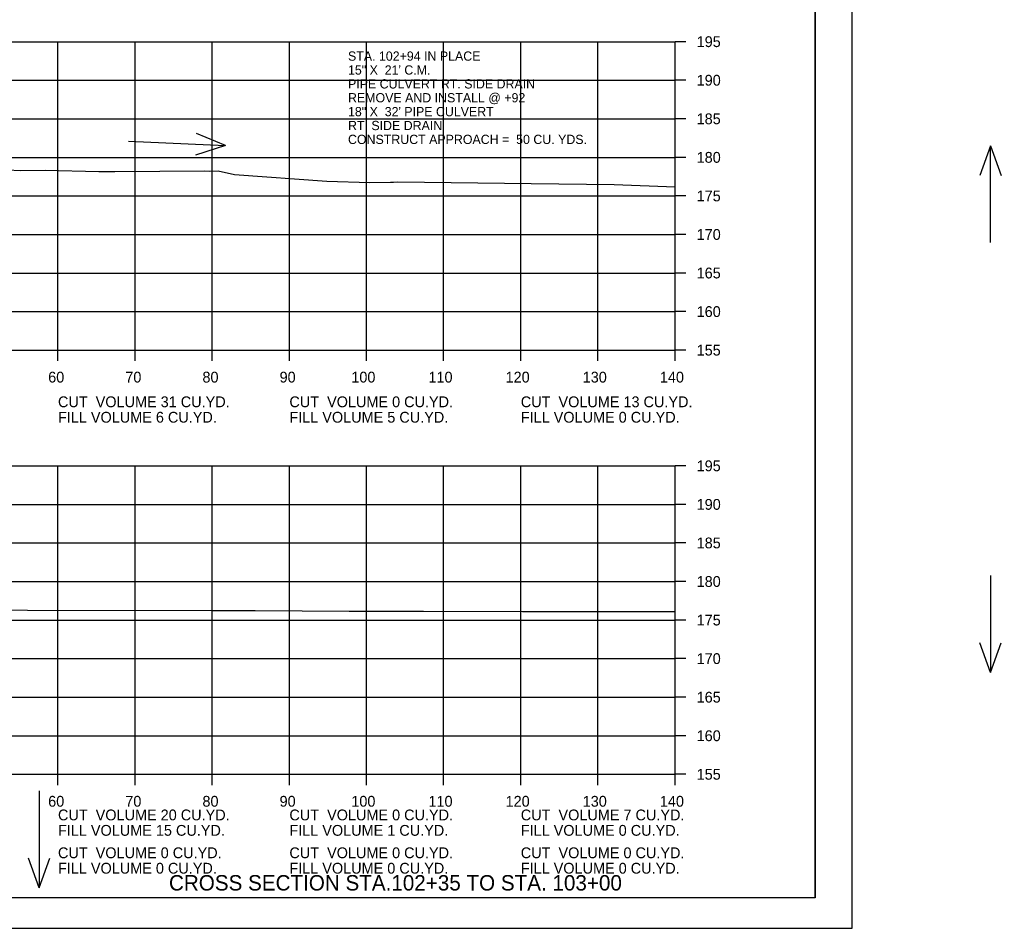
# Model space of a CAD drawing. Extents: x 915787 to 919910, y 133456 to 136717.
# Drawn here: x 916469 to 916596.3, y 133456 to 133573.9 of the extents above; entities that cross this region are included whole.
import ezdxf

# ---------------------------------------------------------------- set-up
doc = ezdxf.new("R2010")
doc.units = 0
for name, color, linetype in [('R_Axis', 7, 'Continuous'), ('R_Axis Annot', 7, 'Continuous'), ('R_Border', 7, 'Continuous'), ('R_Border Notes', 7, 'Continuous'), ('R_Draft', 7, 'Continuous'), ('R_Exist Surface', 7, 'Continuous'), ('R_Grid', 7, 'Continuous'), ('R_No Plot', 7, 'Continuous'), ('R_Water Annot', 7, 'Continuous')]:
    doc.layers.add(name, color=color, linetype=linetype)

msp = doc.modelspace()

# ---------------------------------------------------------------- linework, layer by layer
at = {"layer": 'R_Axis'}
for p, q in [((916553.98, 133531.01), (916553.98, 133571.01)), ((916555.38, 133571.01), (916553.98, 133571.01)), ((916555.38, 133566.01), (916553.98, 133566.01)), ((916555.38, 133561.01), (916553.98, 133561.01)), ((916555.38, 133556.01), (916553.98, 133556.01)), ((916555.38, 133551.01), (916553.98, 133551.01)), ((916555.38, 133546.01), (916553.98, 133546.01)), ((916555.38, 133541.01), (916553.98, 133541.01)), ((916555.38, 133536.01), (916553.98, 133536.01)), ((916273.98, 133531.01), (916553.98, 133531.01)), ((916473.98, 133529.61), (916473.98, 133531.01)), ((916483.98, 133529.61), (916483.98, 133531.01)), ((916493.98, 133529.61), (916493.98, 133531.01)), ((916503.98, 133529.61), (916503.98, 133531.01)), ((916513.98, 133529.61), (916513.98, 133531.01)), ((916523.98, 133529.61), (916523.98, 133531.01)), ((916533.98, 133529.61), (916533.98, 133531.01)), ((916543.98, 133529.61), (916543.98, 133531.01)), ((916553.98, 133529.61), (916553.98, 133531.01)), ((916555.38, 133531.01), (916553.98, 133531.01)), ((916553.98, 133476.01), (916553.98, 133516.01)), ((916555.38, 133516.01), (916553.98, 133516.01)), ((916555.38, 133511.01), (916553.98, 133511.01)), ((916555.38, 133506.01), (916553.98, 133506.01)), ((916555.38, 133501.01), (916553.98, 133501.01)), ((916555.38, 133496.01), (916553.98, 133496.01)), ((916555.38, 133491.01), (916553.98, 133491.01)), ((916555.38, 133486.01), (916553.98, 133486.01)), ((916555.38, 133481.01), (916553.98, 133481.01)), ((916273.98, 133476.01), (916553.98, 133476.01)), ((916473.98, 133474.61), (916473.98, 133476.01)), ((916483.98, 133474.61), (916483.98, 133476.01)), ((916493.98, 133474.61), (916493.98, 133476.01)), ((916503.98, 133474.61), (916503.98, 133476.01)), ((916513.98, 133474.61), (916513.98, 133476.01)), ((916523.98, 133474.61), (916523.98, 133476.01)), ((916533.98, 133474.61), (916533.98, 133476.01)), ((916543.98, 133474.61), (916543.98, 133476.01)), ((916553.98, 133474.61), (916553.98, 133476.01)), ((916555.38, 133476.01), (916553.98, 133476.01))]:
    msp.add_line(p, q, dxfattribs=at)
at = {"layer": 'R_Border'}
for q in [(916572.16, 133665.47), (916255.98, 133460.01)]:
    msp.add_line((916572.16, 133460.01), q, dxfattribs=at)
at = {"layer": 'R_Exist Surface'}
for points in [[(916467.4, 133554.39), (916469.15, 133554.32), (916472.32, 133554.35), (916479.26, 133554.19), (916481.37, 133554.18), (916493.01, 133554.27), (916493.63, 133554.24), (916494.76, 133554.26), (916496.87, 133553.78), (916508.84, 133552.93), (916514.41, 133552.77), (916517.07, 133552.8), (916517.46, 133552.81), (916518.04, 133552.82), (916535.32, 133552.63), (916546.07, 133552.51), (916553.98, 133552.17)], [(916458.75, 133497.39), (916470.01, 133497.28), (916494.02, 133497.27), (916499.56, 133497.26), (916511.72, 133497.18), (916521.35, 133497.18), (916534.19, 133497.13), (916541.82, 133497.12), (916547.25, 133497.11), (916553.98, 133497.14)]]:
    msp.add_lwpolyline(points, dxfattribs=at)
at = {"layer": 'R_Grid'}
for p, q in [((916273.98, 133571.01), (916553.98, 133571.01)), ((916473.98, 133531.01), (916473.98, 133571.01)), ((916483.98, 133531.01), (916483.98, 133571.01)), ((916493.98, 133531.01), (916493.98, 133571.01)), ((916503.98, 133531.01), (916503.98, 133571.01)), ((916513.98, 133531.01), (916513.98, 133571.01)), ((916523.98, 133531.01), (916523.98, 133571.01)), ((916533.98, 133531.01), (916533.98, 133571.01)), ((916543.98, 133531.01), (916543.98, 133571.01)), ((916553.98, 133531.01), (916553.98, 133571.01)), ((916273.98, 133566.01), (916553.98, 133566.01)), ((916273.98, 133561.01), (916553.98, 133561.01)), ((916273.98, 133556.01), (916553.98, 133556.01)), ((916273.98, 133551.01), (916553.98, 133551.01)), ((916273.98, 133546.01), (916553.98, 133546.01)), ((916273.98, 133541.01), (916553.98, 133541.01)), ((916273.98, 133536.01), (916553.98, 133536.01)), ((916273.98, 133531.01), (916553.98, 133531.01)), ((916273.98, 133516.01), (916553.98, 133516.01)), ((916473.98, 133476.01), (916473.98, 133516.01)), ((916483.98, 133476.01), (916483.98, 133516.01)), ((916493.98, 133476.01), (916493.98, 133516.01)), ((916503.98, 133476.01), (916503.98, 133516.01)), ((916513.98, 133476.01), (916513.98, 133516.01)), ((916523.98, 133476.01), (916523.98, 133516.01)), ((916533.98, 133476.01), (916533.98, 133516.01)), ((916543.98, 133476.01), (916543.98, 133516.01)), ((916553.98, 133476.01), (916553.98, 133516.01)), ((916273.98, 133511.01), (916553.98, 133511.01)), ((916273.98, 133506.01), (916553.98, 133506.01)), ((916273.98, 133501.01), (916553.98, 133501.01)), ((916273.98, 133496.01), (916553.98, 133496.01)), ((916273.98, 133491.01), (916553.98, 133491.01)), ((916273.98, 133486.01), (916553.98, 133486.01)), ((916273.98, 133481.01), (916553.98, 133481.01)), ((916273.98, 133476.01), (916553.98, 133476.01))]:
    msp.add_line(p, q, dxfattribs=at)
at = {"layer": 'R_No Plot'}
msp.add_line((916243.57, 133456.04), (916576.91, 133456.04), dxfattribs=at)
for points in [[(916243.57, 133669.37), (916576.91, 133669.37), (916576.91, 133456.03), (916243.57, 133456.03)], [(916489.9, 133665.47), (916489.9, 133655.59), (916525.63, 133655.59), (916525.63, 133652.67), (916548.83, 133652.67), (916548.83, 133629.46), (916572.16, 133629.46), (916572.16, 133460.01), (916255.98, 133460.01), (916255.98, 133665.47)]]:
    msp.add_lwpolyline(points, close=True, dxfattribs=at)
at = {"layer": 'R_Water Annot'}
for p, q in [((916495.7, 133557.53), (916491.92, 133559.11)), ((916483.14, 133558.13), (916495.7, 133557.53)), ((916495.7, 133557.53), (916491.79, 133556.31)), ((916594.88, 133557.52), (916593.48, 133553.67)), ((916594.88, 133544.95), (916594.88, 133557.52)), ((916594.88, 133557.52), (916596.28, 133553.67)), ((916594.88, 133501.78), (916594.88, 133489.21)), ((916594.88, 133489.21), (916593.48, 133493.06)), ((916594.88, 133489.21), (916596.28, 133493.06)), ((916471.54, 133473.85), (916471.54, 133461.28)), ((916471.54, 133461.28), (916470.14, 133465.13)), ((916471.54, 133461.28), (916472.94, 133465.13))]:
    msp.add_line(p, q, dxfattribs=at)

# ---------------------------------------------------------------- texts
at = {"layer": 'R_Axis Annot'}
for s, p in [('195', (916556.78, 133570.31)), ('190', (916556.78, 133565.31)), ('185', (916556.78, 133560.31)), ('180', (916556.78, 133555.31)), ('175', (916556.78, 133550.31)), ('170', (916556.78, 133545.31)), ('165', (916556.78, 133540.31)), ('160', (916556.78, 133535.31)), ('155', (916556.78, 133530.31)), ('60', (916472.71, 133526.81)), ('70', (916482.71, 133526.81)), ('80', (916492.71, 133526.81)), ('90', (916502.71, 133526.81)), ('100', (916512.01, 133526.81)), ('110', (916522.01, 133526.81)), ('120', (916532.01, 133526.81)), ('130', (916542.01, 133526.81)), ('140', (916552.01, 133526.81)), ('195', (916556.78, 133515.31)), ('190', (916556.78, 133510.31)), ('185', (916556.78, 133505.31)), ('180', (916556.78, 133500.31)), ('175', (916556.78, 133495.31)), ('170', (916556.78, 133490.31)), ('165', (916556.78, 133485.31)), ('160', (916556.78, 133480.31)), ('155', (916556.78, 133475.31)), ('60', (916472.71, 133471.81)), ('70', (916482.71, 133471.81)), ('80', (916492.71, 133471.81)), ('90', (916502.71, 133471.81)), ('100', (916512.01, 133471.81)), ('110', (916522.01, 133471.81)), ('120', (916532.01, 133471.81)), ('130', (916542.01, 133471.81)), ('140', (916552.01, 133471.81))]:
    msp.add_text(s, height=1.4, dxfattribs=at).set_placement(p)
at = {"layer": 'R_Border Notes'}
for s, p in [('CUT  VOLUME 31 CU.YD.', (916473.98, 133523.61)), ('CUT  VOLUME 0 CU.YD.', (916503.98, 133523.61)), ('CUT  VOLUME 13 CU.YD.', (916533.98, 133523.61)), ('FILL VOLUME 6 CU.YD.', (916473.98, 133521.61)), ('FILL VOLUME 5 CU.YD.', (916503.98, 133521.61)), ('FILL VOLUME 0 CU.YD.', (916533.98, 133521.61)), ('CUT  VOLUME 20 CU.YD.', (916473.98, 133470.04)), ('CUT  VOLUME 0 CU.YD.', (916503.98, 133470.04)), ('CUT  VOLUME 7 CU.YD.', (916533.98, 133470.04)), ('FILL VOLUME 15 CU.YD.', (916473.98, 133468.04)), ('FILL VOLUME 1 CU.YD.', (916503.98, 133468.04)), ('FILL VOLUME 0 CU.YD.', (916533.98, 133468.04)), ('CUT  VOLUME 0 CU.YD.', (916473.98, 133465.13)), ('CUT  VOLUME 0 CU.YD.', (916503.98, 133465.13)), ('CUT  VOLUME 0 CU.YD.', (916533.98, 133465.13)), ('FILL VOLUME 0 CU.YD.', (916473.98, 133463.13)), ('FILL VOLUME 0 CU.YD.', (916503.98, 133463.13)), ('FILL VOLUME 0 CU.YD.', (916533.98, 133463.13))]:
    msp.add_text(s, height=1.4, dxfattribs=at).set_placement(p)
at = {"layer": 'R_Draft'}
msp.add_text('CROSS SECTION STA.102+35 TO STA. 103+00', height=2, dxfattribs=at).set_placement((916488.37, 133460.94))
at = {"layer": 'R_Water Annot'}
for s, p in [('STA. 102+94 IN PLACE', (916511.58, 133568.54)), ('15" X  21\' C.M.   ', (916511.58, 133566.74)), ('PIPE CULVERT RT. SIDE DRAIN', (916511.58, 133564.94)), ('REMOVE AND INSTALL @ +92', (916511.58, 133563.14)), ('18" X  32\' PIPE CULVERT', (916511.58, 133561.34)), ('RT. SIDE DRAIN', (916511.58, 133559.54)), ('CONSTRUCT APPROACH =  50 CU. YDS.', (916511.58, 133557.74))]:
    msp.add_text(s, height=1.2, dxfattribs=at).set_placement(p)

doc.saveas('drawing.dxf')
